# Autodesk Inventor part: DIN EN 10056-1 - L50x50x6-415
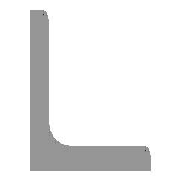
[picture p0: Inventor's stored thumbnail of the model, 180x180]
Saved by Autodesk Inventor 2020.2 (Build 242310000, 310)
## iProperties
_CCFamilyMember: 120
_CCFamilyDisplayName: DIN EN 10056-1 (Warmgewalztes Baustahlprofil - gleichschenklig) - Warmgewalztes Baustahlprofil - gleichschenklig
_FrameMemberDoc: Frame Member File
_Version: 15.0.0
_GetPNFromCC: 1
Created: 2019-01
Part Number: DIN EN 10056-1 - L50x50x6-415
Material: Stahl, weich
Description: Warmgewalztes Baustahlprofil - gleichschenklig
Document SubType Name: Modeling
Standard: DIN
Designer: lutzd
Standard Revision: 1998
Standards Organization: DIN
Language: de-DE
Size Designation: L50x50x6
Categories: <MemberInstance><Categories><Category DisplayName="Profile" InternalName="089c4875-fa83-4c05-b084-43b9cc11f5ed" Mnemonic="GRDR"><CategoryParameter DisplayName="
Stock Number: L50x50x6
Mass: 1823.55 g
Surface Area: 813.077 cm^2
Volume: 232.299 cm^3
Density: 7.85 g/cm^3
Appearance: Semi-Polished(8)
IsCustomPart: 1
G_L: 415,000 mm
G_W: 50,000 mm
G_H: 50,000 mm
+9FD71C4A-1CFE-488F-A9D3-43B11400DDCA+SCHNITTDETAIL1: Schnittwinkel 90,00 grd
+BD68D618-A509-4722-9D9E-F72A72BC7D79+SCHNITTDETAIL2: Schnittwinkel 90,00 grd
DocNumber: ADSK-014305
Folder: .
Dimensions: 50x415x50 mm
Mass: 1,824 kg
VLT_Material: Stahl, weich
Title: Profil-Bauteil
Author: lutzd
Revision Number: -
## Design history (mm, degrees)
node "Startebene"
node "Endebene"
sketch "Skizze"
  geometry: L1 (-8.414, -1.414)-(-8.414, 32.086); L2 (-14.414, 35.586)-(-11.914, 35.586); L3 (-14.414, -14.414)-(-14.414, 35.586); L4 (-14.414, -14.414)-(35.586, -14.414); L5 (35.586, -11.914)-(35.586, -14.414); L6 (-1.414, -8.414)-(32.086, -8.414); L7 (0, 46.456)-(0, -24.559) reference; L8 (-24.559, 0)-(46.456, 0) reference; A1 r 7 centre (-1.414, -1.414) between (-8.414, -1.414) and (-1.414, -8.414); A2 r 3.5 centre (-11.914, 32.086) between (-8.414, 32.086) and (-11.914, 35.586); A3 r 3.5 centre (32.086, -11.914) between (35.586, -11.914) and (32.086, -8.414); 3 further points
  constraints: 12 end point, 6 point on circle, 6 point on line, 6 tangent, 3 centre point, 3 horizontal, 3 vertical, 1 equal radius
  dimensions: "d4" = 50 distance of L3.start L4.end (= b); "d6" = 50 distance of L3.start L2.start (= b); "d8" = 6 distance of point (35.586, -8.414) L4.end (= ParT); "d10" = 6 distance of L2.start point (-8.414, 35.586) (= ParT); "d17" = 7 radius of A1 (= R); "d18" = 3.5 radius of A2 (= R1); "d19" = 14.41385 distance between parallel lines of L8 L4 (= ex); "d20" = 14.41385 distance between parallel lines of L3 L7 (= d19)
extrude "Körper" new body sketch "Skizze" stored distance "d11" = 415 (= G_L); taper "d12" = 0 deg
node "Driven Length"
  sketch "Sketch3"
    geometry: L1 (0, 0)-(10, 0) reference
    constraints: 2 end point, 1 horizontal
  workplane "Work Plane10"
  sketch "Sketch4"
    geometry: L1 (-2, 50)-(12, 50) reference; L2 (-2, 465)-(12, 465) reference
    dimensions: "d24" = 415 distance between parallel lines of L1 L2 (derived)
workplane "Arbeitsebene11"
feature "Trennen1"
workplane "Arbeitsebene12"
feature "Trennen2"
sketch "Skizze5"
  geometry: L1 (114, -14.5)-(139, -14.5); L2 (114, -19.5)-(139, -19.5); L3 (139, -9.5)-(114, -9.5); L4 (276, -14.5)-(301, -14.5); L5 (276, -19.5)-(301, -19.5); L6 (301, -9.5)-(276, -9.5); L7 (0, 0)-(415, 0) reference; A1 r 5 centre (114, -14.5) between (114, -9.5) and (114, -19.5); A2 r 5 centre (139, -14.5) between (139, -19.5) and (139, -9.5); A3 r 5 centre (276, -14.5) between (276, -9.5) and (276, -19.5); A4 r 5 centre (301, -14.5) between (301, -19.5) and (301, -9.5); 4 further points
  constraints: 16 end point, 8 point on circle, 8 tangent, 4 centre point, 3 midpoint, 2 parallel, 2 point on line, 1 horizontal
  dimensions: "d25" = 10 distance between parallel lines of L2 L3 (= d26); "d26" = 10 distance between parallel lines of L5 L6; "d27" = 14.5 distance between parallel lines of L7 L4; "d28" = 25 distance of L5.start L5.end; "d29" = 25 distance of L2.start L2.end (= d28); "d30" = 162 distance of point (288.5, -14.5) point (126.5, -14.5); "d31" = 81 horizontal distance of point (288.5, -14.5) point (207.5, 0) (= 0.5 x d30)
extrude "Extrusion2" cut sketch "Skizze5" distance "d32" = 10; taper "d33" = 0 deg
body "Solid1"
other parameters: "b" = 50 [user parameter; used in 3 equation terms], "ParT" = 6 [user parameter; used in 3 equation terms], "R" = 7 [user parameter; used in 1 equation term], "R1" = 3.5 [user parameter; used in 1 equation term], "G_L" = 415 (= d24) [user parameter; used in 1 equation term], "d7" = 4 (derived), "d9" = 4 (derived), "ex" = 14.41385 (computed from b, ParT) [user parameter; used in 1 equation term], "G_OFFSET_END" = -25 [user parameter; used in 1 equation term], "d22" = 465 (= G_OFFSET_END + B_L), "d23" = 90 deg
